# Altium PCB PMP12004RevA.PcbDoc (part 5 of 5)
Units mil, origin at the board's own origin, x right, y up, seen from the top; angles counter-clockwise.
Board outline 5500 x 4500 mil, 6 copper layers (Top Layer, GND, Signal Layer 1, Signal Layer 2, PWR Split, Bottom Layer), stack 0 mil thick; 355 components, 130 nets, 833 pads, 904 vias.
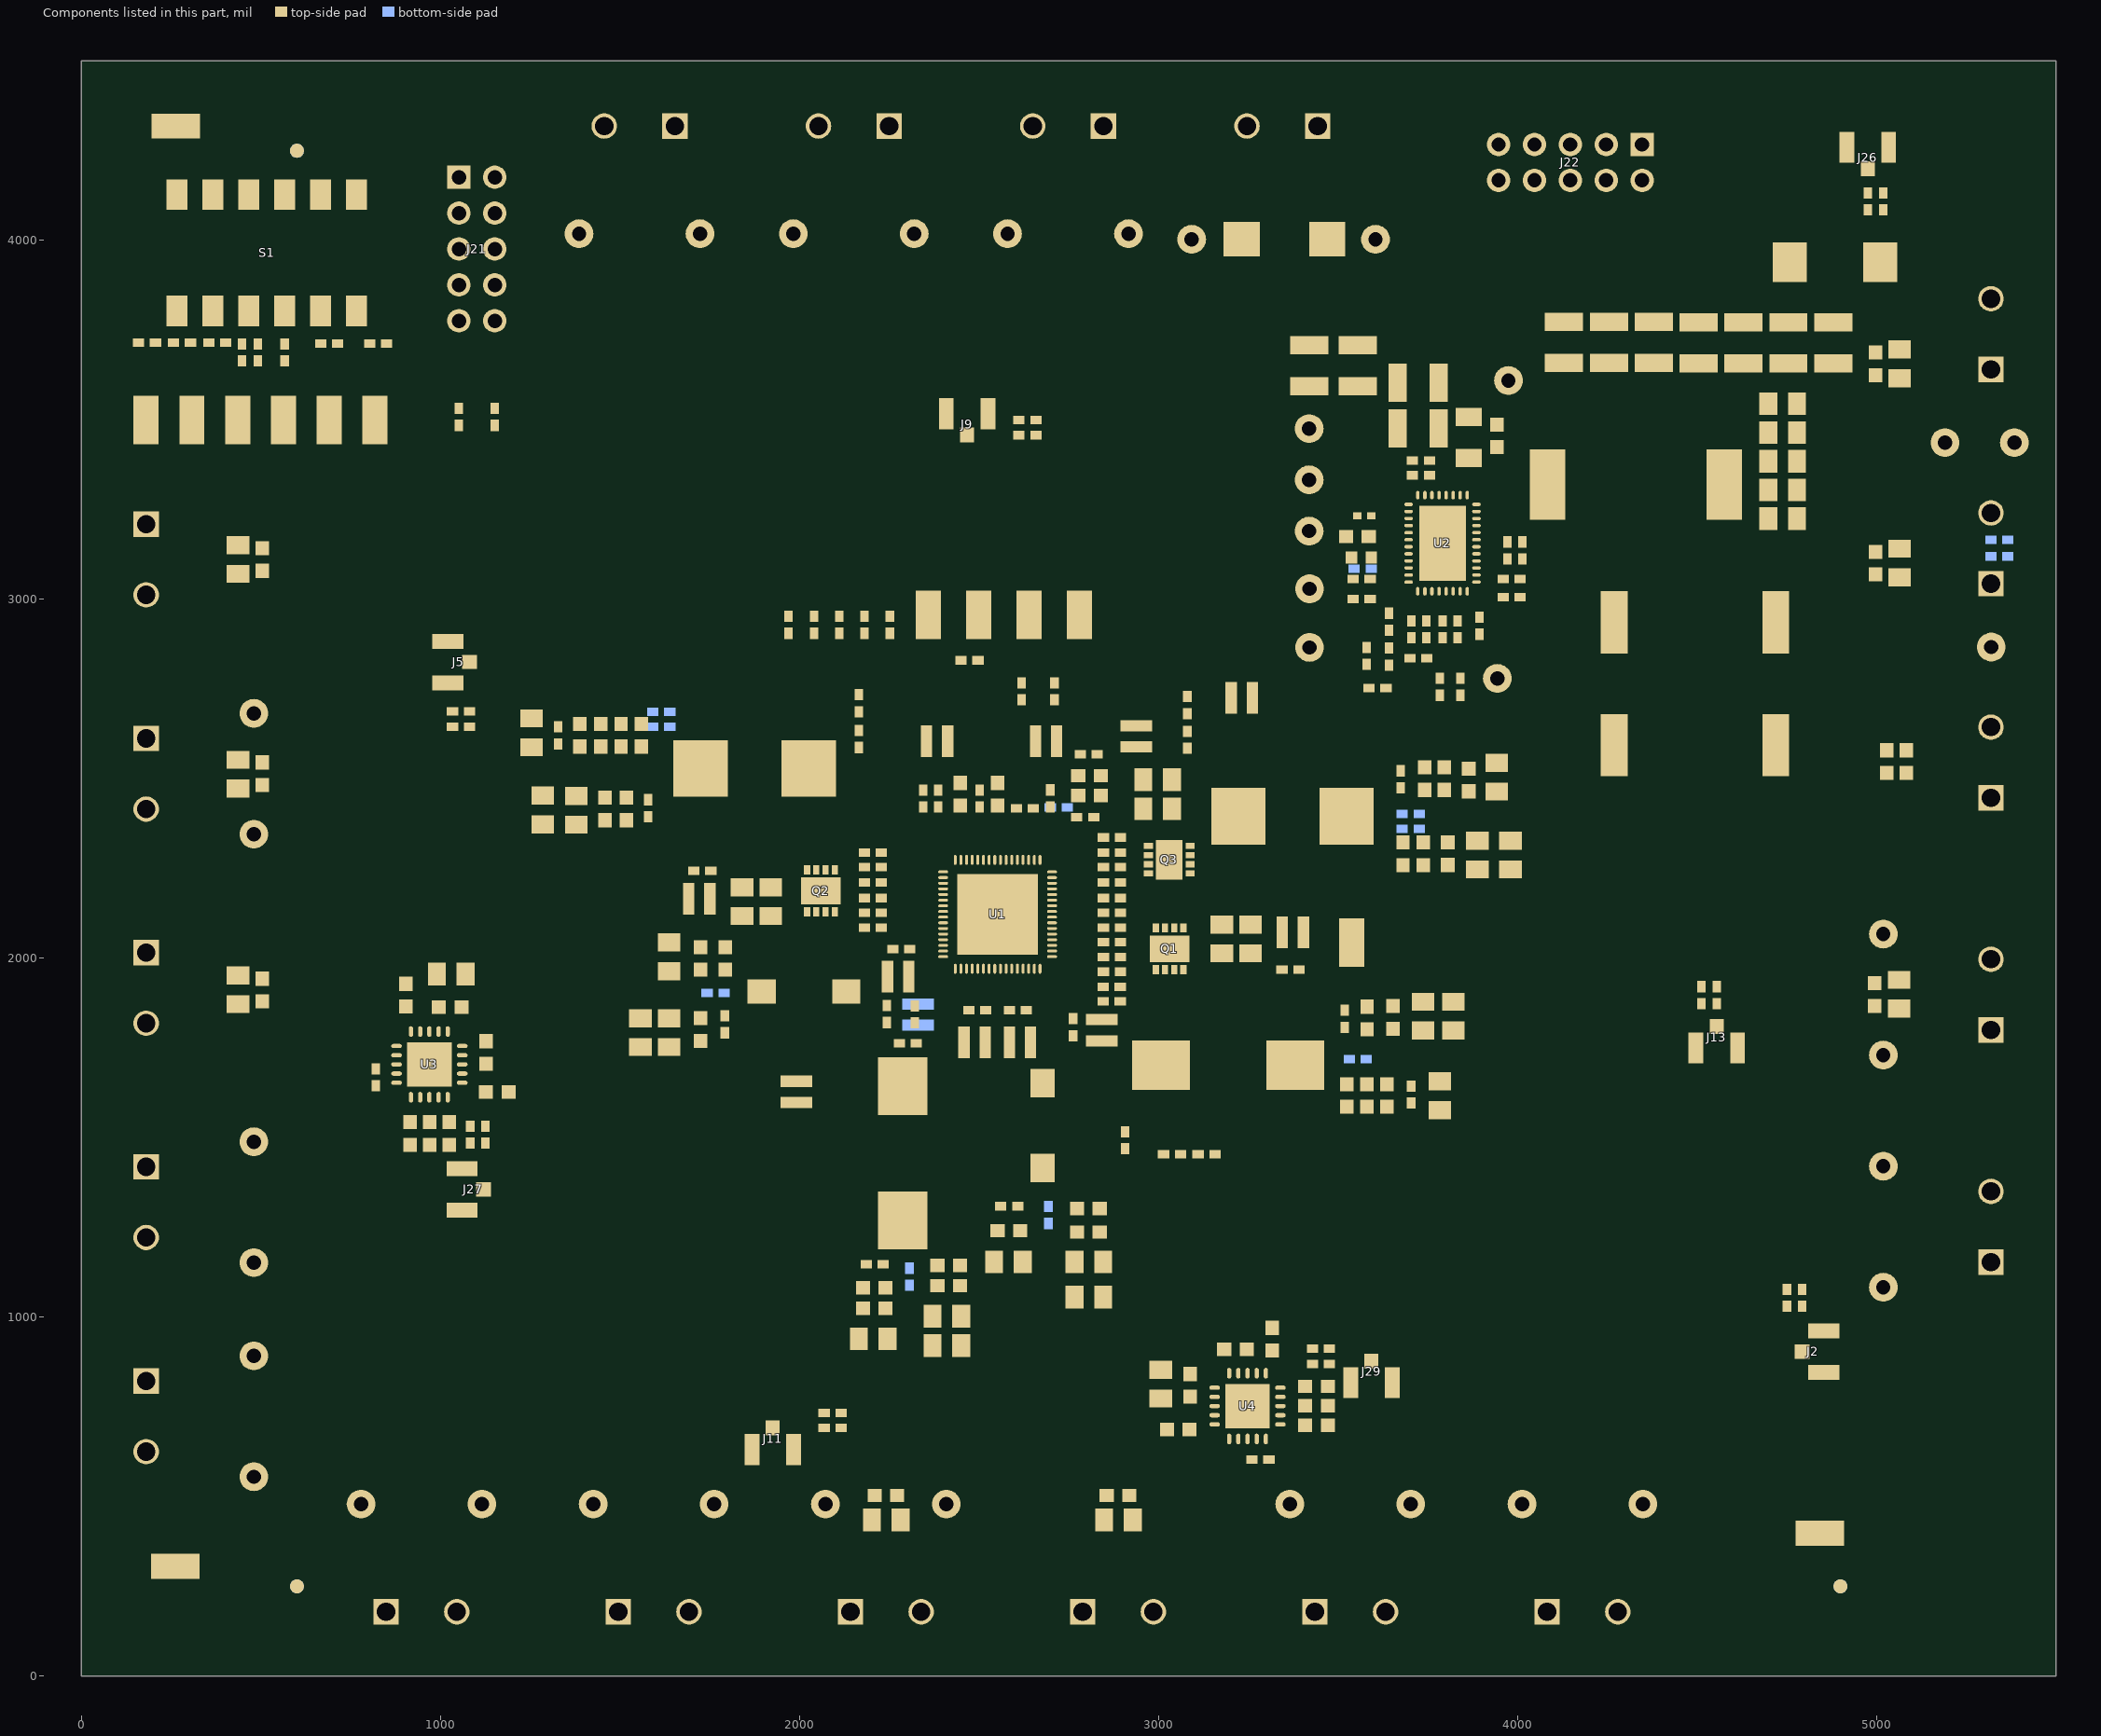
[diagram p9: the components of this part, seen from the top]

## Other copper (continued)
PWR Split:
  pour cut-out: 1335.59,4019 1337.31,4032.05 1342.35,4044.22 1350.36,4054.66 1360.81,4062.67 1372.97,4067.71 1386.02,4069.43 1399.08,4067.71 1411.24,4062.67 1421.69,4054.66 1429.7,4044.22 1434.74,4032.05 1436.46,4019 1434.74,4005.95 1429.7,3993.78 1421.69,3983.34 1411.24,3975.33 1399.08,3970.29 1386.02,3968.57 1372.97,3970.29 1360.81,3975.33 1350.36,3983.34 1342.35,3993.78 1337.31,4005.95
  pour cut-out: 1672.44,4019 1674.16,4032.05 1679.2,4044.22 1687.21,4054.66 1697.66,4062.67 1709.82,4067.71 1722.87,4069.43 1735.93,4067.71 1748.09,4062.67 1758.54,4054.66 1766.55,4044.22 1771.59,4032.05 1773.31,4019 1771.59,4005.95 1766.55,3993.78 1758.54,3983.34 1748.09,3975.33 1735.93,3970.29 1722.87,3968.57 1709.82,3970.29 1697.66,3975.33 1687.21,3983.34 1679.2,3993.78 1674.16,4005.95
  pour cut-out: 1932.44,4019 1934.16,4032.05 1939.2,4044.22 1947.21,4054.66 1957.66,4062.67 1969.82,4067.71 1982.87,4069.43 1995.93,4067.71 2008.09,4062.67 2018.54,4054.66 2026.55,4044.22 2031.59,4032.05 2033.31,4019 2031.59,4005.95 2026.55,3993.78 2018.54,3983.34 2008.09,3975.33 1995.93,3970.29 1982.87,3968.57 1969.82,3970.29 1957.66,3975.33 1947.21,3983.34 1939.2,3993.78 1934.16,4005.95
  pour cut-out: 2269.29,4019 2271.01,4032.05 2276.05,4044.22 2284.06,4054.66 2294.51,4062.67 2306.67,4067.71 2319.72,4069.43 2332.78,4067.71 2344.94,4062.67 2355.39,4054.66 2363.4,4044.22 2368.44,4032.05 2370.16,4019 2368.44,4005.95 2363.4,3993.78 2355.39,3983.34 2344.94,3975.33 2332.78,3970.29 2319.72,3968.57 2306.67,3970.29 2294.51,3975.33 2284.06,3983.34 2276.05,3993.78 2271.01,4005.95
  pour cut-out: 2529.29,4019 2531.01,4032.05 2536.05,4044.22 2544.06,4054.66 2554.51,4062.67 2566.67,4067.71 2579.72,4069.43 2592.78,4067.71 2604.94,4062.67 2615.39,4054.66 2623.4,4044.22 2628.44,4032.05 2630.16,4019 2628.44,4005.95 2623.4,3993.78 2615.39,3983.34 2604.94,3975.33 2592.78,3970.29 2579.72,3968.57 2566.67,3970.29 2554.51,3975.33 2544.06,3983.34 2536.05,3993.78 2531.01,4005.95
  pour cut-out: 2866.14,4019 2867.86,4032.05 2872.9,4044.22 2880.91,4054.66 2891.36,4062.67 2903.52,4067.71 2916.57,4069.43 2929.63,4067.71 2941.79,4062.67 2952.24,4054.66 2960.25,4044.22 2965.29,4032.05 2967.01,4019 2965.29,4005.95 2960.25,3993.78 2952.24,3983.34 2941.79,3975.33 2929.63,3970.29 2916.57,3968.57 2903.52,3970.29 2891.36,3975.33 2880.91,3983.34 2872.9,3993.78 2867.86,4005.95
  pour cut-out: 4968.9,2067.19 4970.62,2080.25 4975.66,2092.41 4983.67,2102.85 4994.12,2110.87 5006.28,2115.91 5019.33,2117.63 5032.38,2115.91 5044.55,2110.87 5054.99,2102.85 5063.01,2092.41 5068.05,2080.25 5069.76,2067.19 5068.05,2054.14 5063.01,2041.98 5054.99,2031.53 5044.55,2023.52 5032.38,2018.48 5019.33,2016.76 5006.28,2018.48 4994.12,2023.52 4983.67,2031.53 4975.66,2041.98 4970.62,2054.14
  pour cut-out: 4968.9,1730.34 4970.62,1743.4 4975.66,1755.56 4983.67,1766 4994.12,1774.02 5006.28,1779.06 5019.33,1780.78 5032.38,1779.06 5044.55,1774.02 5054.99,1766 5063.01,1755.56 5068.05,1743.4 5069.76,1730.34 5068.05,1717.29 5063.01,1705.13 5054.99,1694.68 5044.55,1686.67 5032.38,1681.63 5019.33,1679.91 5006.28,1681.63 4994.12,1686.67 4983.67,1694.68 4975.66,1705.13 4970.62,1717.29
  pour cut-out: 4968.9,1420.34 4970.62,1433.4 4975.66,1445.56 4983.67,1456 4994.12,1464.02 5006.28,1469.06 5019.33,1470.78 5032.38,1469.06 5044.55,1464.02 5054.99,1456 5063.01,1445.56 5068.05,1433.4 5069.76,1420.34 5068.05,1407.29 5063.01,1395.13 5054.99,1384.68 5044.55,1376.67 5032.38,1371.63 5019.33,1369.91 5006.28,1371.63 4994.12,1376.67 4983.67,1384.68 4975.66,1395.13 4970.62,1407.29
  pour cut-out: 4968.9,1083.49 4970.62,1096.55 4975.66,1108.71 4983.67,1119.15 4994.12,1127.17 5006.28,1132.21 5019.33,1133.93 5032.38,1132.21 5044.55,1127.17 5054.99,1119.15 5063.01,1108.71 5068.05,1096.55 5069.76,1083.49 5068.05,1070.44 5063.01,1058.28 5054.99,1047.83 5044.55,1039.82 5032.38,1034.78 5019.33,1033.06 5006.28,1034.78 4994.12,1039.82 4983.67,1047.83 4975.66,1058.28 4970.62,1070.44
  pour cut-out: 4299.24,479 4300.96,492.05 4306,504.22 4314.01,514.66 4324.46,522.67 4336.62,527.71 4349.68,529.43 4362.73,527.71 4374.89,522.67 4385.34,514.66 4393.35,504.22 4398.39,492.05 4400.11,479 4398.39,465.95 4393.35,453.78 4385.34,443.34 4374.89,435.33 4362.73,430.29 4349.68,428.57 4336.62,430.29 4324.46,435.33 4314.01,443.34 4306,453.78 4300.96,465.95
  pour cut-out: 3962.39,479 3964.11,492.05 3969.15,504.22 3977.16,514.66 3987.61,522.67 3999.77,527.71 4012.83,529.43 4025.88,527.71 4038.04,522.67 4048.49,514.66 4056.5,504.22 4061.54,492.05 4063.26,479 4061.54,465.95 4056.5,453.78 4048.49,443.34 4038.04,435.33 4025.88,430.29 4012.83,428.57 3999.77,430.29 3987.61,435.33 3977.16,443.34 3969.15,453.78 3964.11,465.95
  pour cut-out: 3652.39,479 3654.11,492.05 3659.15,504.22 3667.16,514.66 3677.61,522.67 3689.77,527.71 3702.83,529.43 3715.88,527.71 3728.04,522.67 3738.49,514.66 3746.5,504.22 3751.54,492.05 3753.26,479 3751.54,465.95 3746.5,453.78 3738.49,443.34 3728.04,435.33 3715.88,430.29 3702.83,428.57 3689.77,430.29 3677.61,435.33 3667.16,443.34 3659.15,453.78 3654.11,465.95
  pour cut-out: 3315.54,479 3317.26,492.05 3322.3,504.22 3330.31,514.66 3340.76,522.67 3352.92,527.71 3365.98,529.43 3379.03,527.71 3391.19,522.67 3401.64,514.66 3409.65,504.22 3414.69,492.05 3416.41,479 3414.69,465.95 3409.65,453.78 3401.64,443.34 3391.19,435.33 3379.03,430.29 3365.98,428.57 3352.92,430.29 3340.76,435.33 3330.31,443.34 3322.3,453.78 3317.26,465.95
  pour cut-out: 2358.69,479 2360.41,492.05 2365.45,504.22 2373.46,514.66 2383.91,522.67 2396.07,527.71 2409.13,529.43 2422.18,527.71 2434.34,522.67 2444.79,514.66 2452.8,504.22 2457.84,492.05 2459.56,479 2457.84,465.95 2452.8,453.78 2444.79,443.34 2434.34,435.33 2422.18,430.29 2409.13,428.57 2396.07,430.29 2383.91,435.33 2373.46,443.34 2365.45,453.78 2360.41,465.95
  pour cut-out: 2021.84,479 2023.56,492.05 2028.6,504.22 2036.61,514.66 2047.06,522.67 2059.22,527.71 2072.28,529.43 2085.33,527.71 2097.49,522.67 2107.94,514.66 2115.95,504.22 2120.99,492.05 2122.71,479 2120.99,465.95 2115.95,453.78 2107.94,443.34 2097.49,435.33 2085.33,430.29 2072.28,428.57 2059.22,430.29 2047.06,435.33 2036.61,443.34 2028.6,453.78 2023.56,465.95
  pour cut-out: 1711.84,479 1713.56,492.05 1718.6,504.22 1726.61,514.66 1737.06,522.67 1749.22,527.71 1762.28,529.43 1775.33,527.71 1787.49,522.67 1797.94,514.66 1805.95,504.22 1810.99,492.05 1812.71,479 1810.99,465.95 1805.95,453.78 1797.94,443.34 1787.49,435.33 1775.33,430.29 1762.28,428.57 1749.22,430.29 1737.06,435.33 1726.61,443.34 1718.6,453.78 1713.56,465.95
  pour cut-out: 1374.99,479 1376.71,492.05 1381.75,504.22 1389.76,514.66 1400.21,522.67 1412.37,527.71 1425.43,529.43 1438.48,527.71 1450.64,522.67 1461.09,514.66 1469.1,504.22 1474.14,492.05 1475.86,479 1474.14,465.95 1469.1,453.78 1461.09,443.34 1450.64,435.33 1438.48,430.29 1425.43,428.57 1412.37,430.29 1400.21,435.33 1389.76,443.34 1381.75,453.78 1376.71,465.95
  pour cut-out: 1064.99,479 1066.71,492.05 1071.75,504.22 1079.76,514.66 1090.21,522.67 1102.37,527.71 1115.43,529.43 1128.48,527.71 1140.64,522.67 1151.09,514.66 1159.1,504.22 1164.14,492.05 1165.86,479 1164.14,465.95 1159.1,453.78 1151.09,443.34 1140.64,435.33 1128.48,430.29 1115.43,428.57 1102.37,430.29 1090.21,435.33 1079.76,443.34 1071.75,453.78 1066.71,465.95
  pour cut-out: 728.14,479 729.86,492.05 734.9,504.22 742.91,514.66 753.36,522.67 765.52,527.71 778.58,529.43 791.63,527.71 803.79,522.67 814.24,514.66 822.25,504.22 827.29,492.05 829.01,479 827.29,465.95 822.25,453.78 814.24,443.34 803.79,435.33 791.63,430.29 778.58,428.57 765.52,430.29 753.36,435.33 742.91,443.34 734.9,453.78 729.86,465.95
  pour cut-out: 429.57,555.17 431.29,568.23 436.33,580.39 444.34,590.84 454.78,598.85 466.95,603.89 480,605.61 493.05,603.89 505.22,598.85 515.66,590.84 523.67,580.39 528.71,568.23 530.43,555.17 528.71,542.12 523.67,529.96 515.66,519.51 505.22,511.5 493.05,506.46 480,504.74 466.95,506.46 454.78,511.5 444.34,519.51 436.33,529.96 431.29,542.12
  pour cut-out: 429.57,892.02 431.29,905.08 436.33,917.24 444.34,927.69 454.78,935.7 466.95,940.74 480,942.46 493.05,940.74 505.22,935.7 515.66,927.69 523.67,917.24 528.71,905.08 530.43,892.02 528.71,878.97 523.67,866.81 515.66,856.36 505.22,848.35 493.05,843.31 480,841.59 466.95,843.31 454.78,848.35 444.34,856.36 436.33,866.81 431.29,878.97
  pour cut-out: 429.57,1488.87 431.29,1501.93 436.33,1514.09 444.34,1524.54 454.78,1532.55 466.95,1537.59 480,1539.31 493.05,1537.59 505.22,1532.55 515.66,1524.54 523.67,1514.09 528.71,1501.93 530.43,1488.87 528.71,1475.82 523.67,1463.66 515.66,1453.21 505.22,1445.2 493.05,1440.16 480,1438.44 466.95,1440.16 454.78,1445.2 444.34,1453.21 436.33,1463.66 431.29,1475.82
  pour cut-out: 429.57,2345.72 431.29,2358.78 436.33,2370.94 444.34,2381.39 454.78,2389.4 466.95,2394.44 480,2396.16 493.05,2394.44 505.22,2389.4 515.66,2381.39 523.67,2370.94 528.71,2358.78 530.43,2345.72 528.71,2332.67 523.67,2320.51 515.66,2310.06 505.22,2302.05 493.05,2297.01 480,2295.29 466.95,2297.01 454.78,2302.05 444.34,2310.06 436.33,2320.51 431.29,2332.67
  pour cut-out: 429.57,2682.57 431.29,2695.63 436.33,2707.79 444.34,2718.24 454.78,2726.25 466.95,2731.29 480,2733.01 493.05,2731.29 505.22,2726.25 515.66,2718.24 523.67,2707.79 528.71,2695.63 530.43,2682.57 528.71,2669.52 523.67,2657.36 515.66,2646.91 505.22,2638.9 493.05,2633.86 480,2632.14 466.95,2633.86 454.78,2638.9 444.34,2646.91 436.33,2657.36 431.29,2669.52
  pour cut-out: 429.57,1152.02 431.29,1165.08 436.33,1177.24 444.34,1187.69 454.78,1195.7 466.95,1200.74 480,1202.46 493.05,1200.74 505.22,1195.7 515.66,1187.69 523.67,1177.24 528.71,1165.08 530.43,1152.02 528.71,1138.97 523.67,1126.81 515.66,1116.36 505.22,1108.35 493.05,1103.31 480,1101.59 466.95,1103.31 454.78,1108.35 444.34,1116.36 436.33,1126.81 431.29,1138.97
  pour cut-out: 1444.93,2268.2 1558.11,2268.2 1569.61,2279.69 1569.61,2366.5 1559.01,2377.09 1545.94,2377.09 1445.6,2276.75 1444.92,2276.75
  pour cut-out: 2532.84,1730.68 2747.78,1730.68 2748.24,1731.15 2656.78,1822.6 2656.78,1864.67 2648.85,1872.61 2648.85,1998.45 2675.49,2025.09 2818.34,2025.09 2820.61,2027.36 2820.61,2037.57 2800.2,2057.97 2800.2,2104.74 2791.98,2112.96 2783.48,2112.96 2739.8,2069.28 2476.84,2069.28 2345.01,2201.11 2327.72,2201.11 2319.5,2192.89 2319.5,2062.49 2325.16,2056.83 2376.76,2056.83 2436.56,1997.03 2436.56,1949.98 2449.03,1937.51 2484.74,1937.51 2546.25,1876.01 2546.25,1744.78 2531.79,1730.32
  pour cut-out: 3155.1,2453.18 3155.1,2345.39 3141.1,2331.39 3061.33,2331.39 3056.27,2326.34 3056.27,2311.55 3051.22,2306.49 3022.42,2306.49 3018.92,2309.99 3018.92,2325.17 3139.93,2446.18
  pour cut-out: 2835.72,2627.54 2919.59,2543.68 2920.05,2543.68 2920.05,2538.59 2855.25,2473.78 2833.66,2473.78 2833.66,2624.34 2835.72,2626.4
  pour cut-out: 3267.37,1924.06 3041.13,1924.06 2954.53,2010.66 2954.53,2024.78 3177.37,2024.78 3267.4,1934.74 3267.4,1929.64
  pour cut-out: 3422.52,1896.68 3639.23,1896.68 3658.35,1915.8 3658.35,1936.09 3654.08,1940.36 3631.85,1940.36 3622.58,1931.09 3513.35,1931.09 3491.43,1909.17 3426.77,1909.17 3422.61,1905
  pour cut-out: 1089.62,1962.7 1100.02,1952.3 1132.01,1952.3 1144.31,1964.61 1138.87,1970.05 1093.41,1970.05 1089.63,1966.26
  pour cut-out: 5269.66,2867.18 5271.38,2880.23 5276.42,2892.39 5284.43,2902.84 5294.87,2910.85 5307.04,2915.89 5320.09,2917.61 5333.14,2915.89 5345.31,2910.85 5355.75,2902.84 5363.76,2892.39 5368.8,2880.23 5370.52,2867.18 5368.8,2854.12 5363.76,2841.96 5355.75,2831.52 5345.31,2823.5 5333.14,2818.46 5320.09,2816.74 5307.04,2818.46 5294.87,2823.5 5284.43,2831.52 5276.42,2841.96 5271.38,2854.12
  pour cut-out: 2542.72,3561.02 2568.8,3561.02 2584.46,3545.36 2584.46,3520.88 2577.7,3520.88 2542.84,3555.73
  pour cut-out: 521.85,836.9 542.93,857.99 543.22,857.99 546.89,854.32 546.89,843.6 535.88,832.59 525.44,832.59
  text "5" at 5162.44,637.86 h100
  text ".Layer_Name" at 577,-858.49 h60
Bottom Layer:
  pour cut-out: 5293.59,3144.07 5324.82,3144.07 5337.45,3131.44 5337.45,3079.69 5291.24,3079.69 5291.24,3141.71
  pour cut-out: 1335.59,4019 1337.31,4032.05 1342.35,4044.22 1350.36,4054.66 1360.81,4062.67 1372.97,4067.71 1386.02,4069.43 1399.08,4067.71 1411.24,4062.67 1421.69,4054.66 1429.7,4044.22 1434.74,4032.05 1436.46,4019 1434.74,4005.95 1429.7,3993.78 1421.69,3983.34 1411.24,3975.33 1399.08,3970.29 1386.02,3968.57 1372.97,3970.29 1360.81,3975.33 1350.36,3983.34 1342.35,3993.78 1337.31,4005.95
  pour cut-out: 1672.44,4019 1674.16,4032.05 1679.2,4044.22 1687.21,4054.66 1697.66,4062.67 1709.82,4067.71 1722.87,4069.43 1735.93,4067.71 1748.09,4062.67 1758.54,4054.66 1766.55,4044.22 1771.59,4032.05 1773.31,4019 1771.59,4005.95 1766.55,3993.78 1758.54,3983.34 1748.09,3975.33 1735.93,3970.29 1722.87,3968.57 1709.82,3970.29 1697.66,3975.33 1687.21,3983.34 1679.2,3993.78 1674.16,4005.95
  pour cut-out: 1932.44,4019 1934.16,4032.05 1939.2,4044.22 1947.21,4054.66 1957.66,4062.67 1969.82,4067.71 1982.87,4069.43 1995.93,4067.71 2008.09,4062.67 2018.54,4054.66 2026.55,4044.22 2031.59,4032.05 2033.31,4019 2031.59,4005.95 2026.55,3993.78 2018.54,3983.34 2008.09,3975.33 1995.93,3970.29 1982.87,3968.57 1969.82,3970.29 1957.66,3975.33 1947.21,3983.34 1939.2,3993.78 1934.16,4005.95
  pour cut-out: 2269.29,4019 2271.01,4032.05 2276.05,4044.22 2284.06,4054.66 2294.51,4062.67 2306.67,4067.71 2319.72,4069.43 2332.78,4067.71 2344.94,4062.67 2355.39,4054.66 2363.4,4044.22 2368.44,4032.05 2370.16,4019 2368.44,4005.95 2363.4,3993.78 2355.39,3983.34 2344.94,3975.33 2332.78,3970.29 2319.72,3968.57 2306.67,3970.29 2294.51,3975.33 2284.06,3983.34 2276.05,3993.78 2271.01,4005.95
  pour cut-out: 2529.29,4019 2531.01,4032.05 2536.05,4044.22 2544.06,4054.66 2554.51,4062.67 2566.67,4067.71 2579.72,4069.43 2592.78,4067.71 2604.94,4062.67 2615.39,4054.66 2623.4,4044.22 2628.44,4032.05 2630.16,4019 2628.44,4005.95 2623.4,3993.78 2615.39,3983.34 2604.94,3975.33 2592.78,3970.29 2579.72,3968.57 2566.67,3970.29 2554.51,3975.33 2544.06,3983.34 2536.05,3993.78 2531.01,4005.95
  pour cut-out: 2866.14,4019 2867.86,4032.05 2872.9,4044.22 2880.91,4054.66 2891.36,4062.67 2903.52,4067.71 2916.57,4069.43 2929.63,4067.71 2941.79,4062.67 2952.24,4054.66 2960.25,4044.22 2965.29,4032.05 2967.01,4019 2965.29,4005.95 2960.25,3993.78 2952.24,3983.34 2941.79,3975.33 2929.63,3970.29 2916.57,3968.57 2903.52,3970.29 2891.36,3975.33 2880.91,3983.34 2872.9,3993.78 2867.86,4005.95
  pour cut-out: 4968.9,2067.19 4970.62,2080.25 4975.66,2092.41 4983.67,2102.85 4994.12,2110.87 5006.28,2115.91 5019.33,2117.63 5032.38,2115.91 5044.55,2110.87 5054.99,2102.85 5063.01,2092.41 5068.05,2080.25 5069.76,2067.19 5068.05,2054.14 5063.01,2041.98 5054.99,2031.53 5044.55,2023.52 5032.38,2018.48 5019.33,2016.76 5006.28,2018.48 4994.12,2023.52 4983.67,2031.53 4975.66,2041.98 4970.62,2054.14
  pour cut-out: 4968.9,1730.34 4970.62,1743.4 4975.66,1755.56 4983.67,1766 4994.12,1774.02 5006.28,1779.06 5019.33,1780.78 5032.38,1779.06 5044.55,1774.02 5054.99,1766 5063.01,1755.56 5068.05,1743.4 5069.76,1730.34 5068.05,1717.29 5063.01,1705.13 5054.99,1694.68 5044.55,1686.67 5032.38,1681.63 5019.33,1679.91 5006.28,1681.63 4994.12,1686.67 4983.67,1694.68 4975.66,1705.13 4970.62,1717.29
  pour cut-out: 4968.9,1420.34 4970.62,1433.4 4975.66,1445.56 4983.67,1456 4994.12,1464.02 5006.28,1469.06 5019.33,1470.78 5032.38,1469.06 5044.55,1464.02 5054.99,1456 5063.01,1445.56 5068.05,1433.4 5069.76,1420.34 5068.05,1407.29 5063.01,1395.13 5054.99,1384.68 5044.55,1376.67 5032.38,1371.63 5019.33,1369.91 5006.28,1371.63 4994.12,1376.67 4983.67,1384.68 4975.66,1395.13 4970.62,1407.29
  pour cut-out: 4968.9,1083.49 4970.62,1096.55 4975.66,1108.71 4983.67,1119.15 4994.12,1127.17 5006.28,1132.21 5019.33,1133.93 5032.38,1132.21 5044.55,1127.17 5054.99,1119.15 5063.01,1108.71 5068.05,1096.55 5069.76,1083.49 5068.05,1070.44 5063.01,1058.28 5054.99,1047.83 5044.55,1039.82 5032.38,1034.78 5019.33,1033.06 5006.28,1034.78 4994.12,1039.82 4983.67,1047.83 4975.66,1058.28 4970.62,1070.44
  pour cut-out: 4299.24,479 4300.96,492.05 4306,504.22 4314.01,514.66 4324.46,522.67 4336.62,527.71 4349.68,529.43 4362.73,527.71 4374.89,522.67 4385.34,514.66 4393.35,504.22 4398.39,492.05 4400.11,479 4398.39,465.95 4393.35,453.78 4385.34,443.34 4374.89,435.33 4362.73,430.29 4349.68,428.57 4336.62,430.29 4324.46,435.33 4314.01,443.34 4306,453.78 4300.96,465.95
  pour cut-out: 3962.39,479 3964.11,492.05 3969.15,504.22 3977.16,514.66 3987.61,522.67 3999.77,527.71 4012.83,529.43 4025.88,527.71 4038.04,522.67 4048.49,514.66 4056.5,504.22 4061.54,492.05 4063.26,479 4061.54,465.95 4056.5,453.78 4048.49,443.34 4038.04,435.33 4025.88,430.29 4012.83,428.57 3999.77,430.29 3987.61,435.33 3977.16,443.34 3969.15,453.78 3964.11,465.95
  pour cut-out: 3652.39,479 3654.11,492.05 3659.15,504.22 3667.16,514.66 3677.61,522.67 3689.77,527.71 3702.83,529.43 3715.88,527.71 3728.04,522.67 3738.49,514.66 3746.5,504.22 3751.54,492.05 3753.26,479 3751.54,465.95 3746.5,453.78 3738.49,443.34 3728.04,435.33 3715.88,430.29 3702.83,428.57 3689.77,430.29 3677.61,435.33 3667.16,443.34 3659.15,453.78 3654.11,465.95
  pour cut-out: 3315.54,479 3317.26,492.05 3322.3,504.22 3330.31,514.66 3340.76,522.67 3352.92,527.71 3365.98,529.43 3379.03,527.71 3391.19,522.67 3401.64,514.66 3409.65,504.22 3414.69,492.05 3416.41,479 3414.69,465.95 3409.65,453.78 3401.64,443.34 3391.19,435.33 3379.03,430.29 3365.98,428.57 3352.92,430.29 3340.76,435.33 3330.31,443.34 3322.3,453.78 3317.26,465.95
  pour cut-out: 2358.69,479 2360.41,492.05 2365.45,504.22 2373.46,514.66 2383.91,522.67 2396.07,527.71 2409.13,529.43 2422.18,527.71 2434.34,522.67 2444.79,514.66 2452.8,504.22 2457.84,492.05 2459.56,479 2457.84,465.95 2452.8,453.78 2444.79,443.34 2434.34,435.33 2422.18,430.29 2409.13,428.57 2396.07,430.29 2383.91,435.33 2373.46,443.34 2365.45,453.78 2360.41,465.95
  pour cut-out: 2021.84,479 2023.56,492.05 2028.6,504.22 2036.61,514.66 2047.06,522.67 2059.22,527.71 2072.28,529.43 2085.33,527.71 2097.49,522.67 2107.94,514.66 2115.95,504.22 2120.99,492.05 2122.71,479 2120.99,465.95 2115.95,453.78 2107.94,443.34 2097.49,435.33 2085.33,430.29 2072.28,428.57 2059.22,430.29 2047.06,435.33 2036.61,443.34 2028.6,453.78 2023.56,465.95
  pour cut-out: 1711.84,479 1713.56,492.05 1718.6,504.22 1726.61,514.66 1737.06,522.67 1749.22,527.71 1762.28,529.43 1775.33,527.71 1787.49,522.67 1797.94,514.66 1805.95,504.22 1810.99,492.05 1812.71,479 1810.99,465.95 1805.95,453.78 1797.94,443.34 1787.49,435.33 1775.33,430.29 1762.28,428.57 1749.22,430.29 1737.06,435.33 1726.61,443.34 1718.6,453.78 1713.56,465.95
  pour cut-out: 1374.99,479 1376.71,492.05 1381.75,504.22 1389.76,514.66 1400.21,522.67 1412.37,527.71 1425.43,529.43 1438.48,527.71 1450.64,522.67 1461.09,514.66 1469.1,504.22 1474.14,492.05 1475.86,479 1474.14,465.95 1469.1,453.78 1461.09,443.34 1450.64,435.33 1438.48,430.29 1425.43,428.57 1412.37,430.29 1400.21,435.33 1389.76,443.34 1381.75,453.78 1376.71,465.95
  pour cut-out: 1064.99,479 1066.71,492.05 1071.75,504.22 1079.76,514.66 1090.21,522.67 1102.37,527.71 1115.43,529.43 1128.48,527.71 1140.64,522.67 1151.09,514.66 1159.1,504.22 1164.14,492.05 1165.86,479 1164.14,465.95 1159.1,453.78 1151.09,443.34 1140.64,435.33 1128.48,430.29 1115.43,428.57 1102.37,430.29 1090.21,435.33 1079.76,443.34 1071.75,453.78 1066.71,465.95
  pour cut-out: 728.14,479 729.86,492.05 734.9,504.22 742.91,514.66 753.36,522.67 765.52,527.71 778.58,529.43 791.63,527.71 803.79,522.67 814.24,514.66 822.25,504.22 827.29,492.05 829.01,479 827.29,465.95 822.25,453.78 814.24,443.34 803.79,435.33 791.63,430.29 778.58,428.57 765.52,430.29 753.36,435.33 742.91,443.34 734.9,453.78 729.86,465.95
  pour cut-out: 429.57,555.17 431.29,568.23 436.33,580.39 444.34,590.84 454.78,598.85 466.95,603.89 480,605.61 493.05,603.89 505.22,598.85 515.66,590.84 523.67,580.39 528.71,568.23 530.43,555.17 528.71,542.12 523.67,529.96 515.66,519.51 505.22,511.5 493.05,506.46 480,504.74 466.95,506.46 454.78,511.5 444.34,519.51 436.33,529.96 431.29,542.12
  pour cut-out: 429.57,892.02 431.29,905.08 436.33,917.24 444.34,927.69 454.78,935.7 466.95,940.74 480,942.46 493.05,940.74 505.22,935.7 515.66,927.69 523.67,917.24 528.71,905.08 530.43,892.02 528.71,878.97 523.67,866.81 515.66,856.36 505.22,848.35 493.05,843.31 480,841.59 466.95,843.31 454.78,848.35 444.34,856.36 436.33,866.81 431.29,878.97
  pour cut-out: 429.57,1488.87 431.29,1501.93 436.33,1514.09 444.34,1524.54 454.78,1532.55 466.95,1537.59 480,1539.31 493.05,1537.59 505.22,1532.55 515.66,1524.54 523.67,1514.09 528.71,1501.93 530.43,1488.87 528.71,1475.82 523.67,1463.66 515.66,1453.21 505.22,1445.2 493.05,1440.16 480,1438.44 466.95,1440.16 454.78,1445.2 444.34,1453.21 436.33,1463.66 431.29,1475.82
  pour cut-out: 429.57,2345.72 431.29,2358.78 436.33,2370.94 444.34,2381.39 454.78,2389.4 466.95,2394.44 480,2396.16 493.05,2394.44 505.22,2389.4 515.66,2381.39 523.67,2370.94 528.71,2358.78 530.43,2345.72 528.71,2332.67 523.67,2320.51 515.66,2310.06 505.22,2302.05 493.05,2297.01 480,2295.29 466.95,2297.01 454.78,2302.05 444.34,2310.06 436.33,2320.51 431.29,2332.67
  pour cut-out: 429.57,2682.57 431.29,2695.63 436.33,2707.79 444.34,2718.24 454.78,2726.25 466.95,2731.29 480,2733.01 493.05,2731.29 505.22,2726.25 515.66,2718.24 523.67,2707.79 528.71,2695.63 530.43,2682.57 528.71,2669.52 523.67,2657.36 515.66,2646.91 505.22,2638.9 493.05,2633.86 480,2632.14 466.95,2633.86 454.78,2638.9 444.34,2646.91 436.33,2657.36 431.29,2669.52
  pour cut-out: 429.57,1152.02 431.29,1165.08 436.33,1177.24 444.34,1187.69 454.78,1195.7 466.95,1200.74 480,1202.46 493.05,1200.74 505.22,1195.7 515.66,1187.69 523.67,1177.24 528.71,1165.08 530.43,1152.02 528.71,1138.97 523.67,1126.81 515.66,1116.36 505.22,1108.35 493.05,1103.31 480,1101.59 466.95,1103.31 454.78,1108.35 444.34,1116.36 436.33,1126.81 431.29,1138.97
  pour cut-out: 1354.44,509.36 1354.44,439.89 1390.08,404.26 1546.78,404.26 1605.71,463.19 1605.71,1244.09 2074.64,1713.02 2239.37,1713.02 2270.07,1743.72 2270.07,1785.34 2260.19,1795.21 2237.97,1795.21 2227.6,1784.84 2227.6,1768.71 2215.51,1756.62 2051.77,1756.62 1557.94,1262.79 1557.94,519.21 1542.98,504.24 1493.95,504.24 1455.83,542.36 1387.45,542.36
  pour cut-out: 2138.36,2215.6 2300.22,2215.6 2327.24,2188.58 2297.69,2159.03 2281.56,2175.16 2138.36,2175.16
  pour cut-out: 2791.5,2138.15 2834.22,2138.15 2856.2,2160.13 2973.03,2160.13 3029.62,2216.72 3061.33,2185.01 2995.7,2119.37 2879.8,2119.37 2853.81,2093.38 2782.38,2093.38 2764.55,2111.2
  pour cut-out: 2785.08,2066.9 2833.02,2066.9 2854.29,2045.62 2952.65,2045.62 2952.65,1995.71 2815.66,1995.71 2785.08,2026.29
  pour cut-out: 5269.66,2867.18 5271.38,2880.23 5276.42,2892.39 5284.43,2902.84 5294.87,2910.85 5307.04,2915.89 5320.09,2917.61 5333.14,2915.89 5345.31,2910.85 5355.75,2902.84 5363.76,2892.39 5368.8,2880.23 5370.52,2867.18 5368.8,2854.12 5363.76,2841.96 5355.75,2831.52 5345.31,2823.5 5333.14,2818.46 5320.09,2816.74 5307.04,2818.46 5294.87,2823.5 5284.43,2831.52 5276.42,2841.96 5271.38,2854.12
  pour cut-out: 2310.49,2160.97 cw(c2310.49,2175.97) 2295.49,2175.97 cw(c2310.49,2175.97) 2310.49,2190.97 cw(c2310.49,2175.97) 2325.49,2175.97 cw(c2310.49,2175.97)
  pour cut-out: 2780.69,2112.34 cw(c2780.69,2127.34) 2765.69,2127.34 cw(c2780.69,2127.34) 2780.69,2142.34 cw(c2780.69,2127.34) 2795.69,2127.34 cw(c2780.69,2127.34)
  pour cut-out: 2785.08,2036.6 cw(c2785.08,2051.6) 2770.08,2051.6 cw(c2785.08,2051.6) 2785.08,2066.6 cw(c2785.08,2051.6) 2800.08,2051.6 cw(c2785.08,2051.6)
  pour cut-out: 3037.13,2179.63 cw(c3037.13,2194.63) 3022.13,2194.63 cw(c3037.13,2194.63) 3037.13,2209.63 cw(c3037.13,2194.63) 3052.13,2194.63 cw(c3037.13,2194.63)
  pour cut-out: 2952.65,2003.85 cw(c2952.65,2018.85) 2937.65,2018.85 cw(c2952.65,2018.85) 2952.65,2033.85 cw(c2952.65,2018.85) 2967.65,2018.85 cw(c2952.65,2018.85)
  pour cut-out: 2138.36,2180.07 cw(c2138.36,2195.07) 2123.36,2195.07 cw(c2138.36,2195.07) 2138.36,2210.07 cw(c2138.36,2195.07) 2153.36,2195.07 cw(c2138.36,2195.07)
  text "6" at 5382.44,636.86 h100
  text ".Layer_Name" at 577,-858.49 h60

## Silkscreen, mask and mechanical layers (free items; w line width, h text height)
Top Overlay:
  circle w6: c4074.91,1962.52 r32
  circle w6: c2774.33,2199.63 r32
  circle w6: c3643.02,3224.19 r25.32
  circle w6: c1961.21,3576 r25.32
  region: 1649.65,978.8 1349.65,978.8 1349.65,878.8 1649.65,878.8
  lines w6: 884.73,1432.65 893.19,1441.72 ; 3504.5,662.94 3520.44,647.01
  lines w6.1: 509.05,1697.24 642.16,1830.35 642.16,3186.72 520.72,3308.16 ; 1547.91,2101.3 1559.18,2090.03 1783.45,2090.03 ; 1678.82,1908.43 1684.07,1908.43 1700.78,1925.14 ; 1946.56,487.8 2024.33,565.57 2084.78,626.02 2976.17,626.02 ; 2119.08,2283.01 2138.71,2302.64 2138.71,2326.67 ; 2196.89,1735.87 2220.63,1759.61 2220.63,1782.89 ; 2592.42,1097.41 2592.42,996.88 2597.1,992.2 ; 2755.42,2600.64 2755.42,2724.12 2764.87,2733.56 ; 2804.83,1956.1 2772.67,1956.1 2728.49,2000.28 2728.49,2300.12 2789.87,2361.51 2805.58,2361.51 ; 2976.65,625.85 3114.62,487.87 ; 3494.98,2822.28 3510.69,2837.99 3543.81,2837.99 ; 3587.9,3253.84 3593.76,3259.7 3632.63,3259.7 3660.39,3259.7 3677.42,3242.67 3677.42,3203.83 3641.78,3168.2 3641.78,3028.37 3681.89,2988.26 3900.77,2988.26 3919.58,3007.07 3919.58,3072.46 3927.99,3080.87 ; 3686.08,3684.06 3686.08,3705.18 3702.32,3721.43 ; 4704.91,3832.23 4728.31,3832.23 4740.83,3819.72 ; 4798.75,3083.23 4813.8,3098.28 4813.8,3170.15 ; 1696.47,3486.78 1696.47,3719.37 1724.94,3747.84 1953.39,3747.84 2179.57,3521.67 2179.57,3424.8 2078.52,3323.75 1859.5,3323.75 1696.47,3486.78 ; 4021.19,1732.87 4021.19,2077.5 4100.2,2156.51 4183.89,2156.51 4238.31,2102.09 4238.31,1694.59 4203.54,1659.81 4094.25,1659.81 4021.19,1732.87
  lines w10: 5074.11,4023.23 5074.11,4085.31 5477.66,4085.31 ; 5075.67,2307.49 5075.67,2231.11 5481,2231.11
  text "GND" at 222.62,4376.69 h30
  text "VTT" at 2526.45,4316.49 h50 r90
  text "VSYS" at 3120.46,4266.51 h50 r90
  text "LDOA2" at 1832.92,4216.53 h50 r90
  text "LDOA3" at 1930.46,4216.53 h50 r90
  text "TPS544C25" at 5112.96,4205.05 h40
  text "1" at 261.39,4183.48 h30
  text "2" at 353.76,4183.48 h30
  text "3" at 452.78,4183.48 h30
  text "4" at 538.97,4183.48 h30
  text "5" at 652.29,4183.48 h30
  text "6" at 754.69,4183.48 h30
  text "_VOUT" at 5272.29,4134.98 h40
  text "VCCINT" at 5198.43,3968.77 h50
  text "GND" at 3567.22,3896.33 h30
  text "GND" at 2283.35,3862.82 h30
  text "GND" at 2884.56,3860.7 h30
  text "GND" at 1689.31,3857.7 h30
  text "B" at 1954.11,3563.22 h25
  text "VSYS" at 3228.89,3407.81 h30
  text "VOUTS+" at 4968.84,3357.31 h30
  text "CTL1" at 122.08,3330.57 h30
  text "CTL2" at 257.68,3330.57 h30
  text "CTL3" at 396.03,3330.57 h30
  text "CTL4" at 532.85,3330.57 h30
  text "CTL5" at 664.2,3330.57 h30
  text "CTL6" at 799.5,3330.57 h30
  text "SMBALERT" at 3127.9,3269.03 h30
  text "B" at 3635.29,3211.26 h25
  text "VREF" at 2815.11,3056.64 h30 r90
  text "LDO3P3" at 2677.15,3056.26 h30 r90
  text "V5ANA" at 2391.87,3054.99 h30 r90
  text "VSYS_IN" at 2536.8,3055.07 h30 r90
  text "VCCINT_IO" at 4943.95,2977.51 h50 r90
  text "VCCPSINTLP" at 18.55,2838.42 h50
  text "GND" at 5152.79,2808.03 h30
  text "GND" at 539.83,2727.36 h30
  text "BUCK2" at 736.81,2369.03 h50 r90
  text "VCCBRAM" at 5125.37,2266.94 h50
  text "VCCPSINTFP" at 18.55,2215.29 h50
  text "A" at 2764.2,2185.86 h30
  text "VCCODDR" at 5140.12,2124.02 h50
  text "A" at 4064.79,1948.75 h30
  text "BUCK6" at 4895,1867.2 h50 r90
  text "VCCPSDDR" at 18.55,1641.28 h50
  text "GND" at 4889.04,1591.65 h30
  text "3.3V@5A" at 5148.45,1477.14 h50
  text "GND" at 437.88,1385.51 h30
  text "BUCK3" at 634.92,1191.66 h50 r90
  text "BUCK1" at 4943.85,1142.72 h50 r90
  text "VMGTAVTT" at 18.55,1046.49 h50
  text "GND" at 4964.35,927.46 h30
  text ".PRJ_Number" at 783.67,898.81 h60
  text "-" at 1279.65,898.81 h60
  text "GND" at 441.11,789.71 h30
  text "XILINX RRH & WIRELESS BH" at 783.04,779.14 h60
  text ".PCB_Rev" at 787.55,678.06 h60
  text "BUCK5" at 2410.06,659.67 h50
  text "BUCK4" at 3416.88,535.49 h50
  text "GND" at 4087.05,446.4 h30
  text "LDOA1" at 25.84,427.9 h50
  text "GND" at 3418.65,403.6 h30
  text "GND" at 1385.41,378.46 h30
  text "GND" at 737.79,377.31 h30
  text "GND" at 2027.32,347.38 h30 r90
  text "GND" at 4803.41,308.77 h30
  text "SWB1" at 1223.94,58.72 h50 r90
  text "SWA1" at 4458.56,54.03 h50 r90
  text "SWB2" at 1870.4,49.35 h50 r90
  text "VCCPSPLL" at 2518.16,27.68 h50 r90
  text "VCCPSAUX" at 3164.58,27.68 h50 r90
  text "VMGTAVCC" at 3813.46,27.68 h50 r90
  text ".Layer_Name" at 577,-858.49 h60
Bottom Overlay:
  text ".Layer_Name" at 577,-858.49 h60
Top Paste:
  text ".Layer_Name" at 577,-858.49 h60
Bottom Paste:
  text ".Layer_Name" at 577,-858.49 h60
Top Solder:
  text ".Layer_Name" at 577,-858.49 h60
  text ".Layer_Name" at 577,-858.49 h60
Bottom Solder:
  text ".Layer_Name" at 577,-858.49 h60
Drill Guide:
  text ".Layer_Name" at 577,-858.49 h60
M1 Board Outline:
  the board outline again, w10
M2 Board Dimensions:
  rectangle: 383.26,-404.49 758.26,-279.49
  rectangle: 258.26,-279.49 383.26,-154.49
  lines w7: 258.26,-279.49 1258.26,-279.49 ; 383.26,-404.49 383.26,-154.49 ; 508.26,-404.49 508.26,-154.49 ; 758.26,-404.49 758.26,-154.49 ; 1008.26,-404.49 1008.26,-154.49 ; 258.26,-404.49 258.26,-154.49 1258.26,-154.49 1258.26,-404.49 258.26,-404.49
  lines w10: -92.71,-90.7 -17.08,-15.07 ; -49.84,-15.07 -17.08,-15.07 ; -17.08,-47.82 -17.08,-15.07
  text "(0,0)" at -251.39,-166.95 h50
M3 3D STEP Top:
  text ".Layer_Name" at 577,-858.49 h60
M4 3D STEP Bottom:
  text ".Layer_Name" at 577,-858.49 h60
M5 Assembly Top:
  lines w6.1: 1630.74,2285.06 2118.93,2285.06 2118.93,2773.27 1630.74,2773.27 1630.74,2285.06 ; 3129.33,2151.44 3129.33,2639.65 3617.52,2639.65 3617.52,2151.44 3129.33,2151.44
  lines w10: -292,-930.17 6308,-930.17 ; -292,-726.83 6310,-726.83 ; -292,-523.5 -292,-1133.5 3713,-1133.5 6310,-1133.5 6310,-523.5 -291.5,-523.5 -291.5,-1133.5 1284,-1133.5 ; 2173,-1133.5 2173,-523.5 ; 3440,-726.83 3440,-523.5 ; 4280,-726.83 4280,-523.5 ; 4902,-1140 4902,-937.17
  text "PCB VIEWED FROM TOP SIDE" at -228.5,-655.67 h60
  text "BOARD #:" at 2248,-655.67 h60
  text ".PRJ_Number" at 2793.5,-655.67 h60
  text "REV:" at 3638,-655.67 h60
  text ".PCB_Rev" at 3929.5,-655.67 h60
  text "SVN REV:" at 4476,-655.67 h60
  text ".VersionControl_RevNumber" at 4982,-655.67 h60
  text "LAYER NAME =" at -228.5,-858.49 h60
  text ".Layer_Name" at 577,-858.49 h60
  text "TID #:" at 2248,-859 h60
  text ".TID" at 2793.5,-859 h60
  text "GENERATED    :" at 2250,-1064.34 h60
  text ".Print_Date" at 3119.5,-1064.34 h60
  text ".Print_Time" at 3848.5,-1064.34 h60
  text "TEXAS INSTRUMENTS" at 5113,-1064.34 h60
M6 Assembly Bottom:
  lines w10: -292.5,-727.33 6309.5,-727.33 ; -290.5,-930.67 6309.5,-930.67 ; 1115.5,-1140.5 1115.5,-937.67 ; 1737.5,-727.33 1737.5,-524 ; 2577.5,-727.33 2577.5,-524 ; 3844.5,-1134 3844.5,-524 ; 4733.5,-1134 6309,-1134 6309,-524 -292.5,-524 -292.5,-1134 2304.5,-1134 6309.5,-1134 6309.5,-524
  text ".VersionControl_RevNumber" at 1035.5,-656.17 h60
  text "SVN REV:" at 1541.5,-656.17 h60
  text ".PCB_Rev" at 2088,-656.17 h60
  text "REV:" at 2379.5,-656.17 h60
  text ".PRJ_Number" at 3224,-656.17 h60
  text "BOARD #:" at 3769.5,-656.17 h60
  text "PCB VIEWED FROM BOTTOM SIDE" at 6246,-656.17 h60
  text ".TID" at 3224,-859.5 h60
  text "TID #:" at 3769.5,-859.5 h60
  text ".Layer_Name" at 5472.69,-864.21 h60
  text "LAYER NAME =" at 6245.57,-868.43 h60
  text "TEXAS INSTRUMENTS" at 904.5,-1064.84 h60
  text ".Print_Time" at 2169,-1064.84 h60
  text ".Print_Date" at 2898,-1064.84 h60
  text "GENERATED    :" at 3767.5,-1064.84 h60
M9 Title Sheet:
  drawing of 57 lines, arcs and shapes, not listed
  text "1" at 739.84,8036.5 h70
  text "2" at 3235.5,8036.5 h70
  text "3" at 5724.84,8036.5 h70
  text "4" at 8231.51,8036.5 h70
  text "5" at 10730.5,8036.5 h70
  text "6" at 13235.5,8036.5 h70
  text "A" at -416.5,6893.5 h70
  text "A" at 14383.5,6893.5 h70
  text "B" at -416.5,4513.5 h70
  text "B" at 14383.5,4513.5 h70
  text "C" at -416.5,2138.5 h70
  text "C" at 14383.5,2138.5 h70
  text "PROJECT TITLE:" at 11343.5,277.5 h45
  text ".PRJ_Title" at 11393.5,144.17 h70
  text "DESIGNED FOR:" at 11343.5,-23.5 h45
  text ".PRJ_Customer" at 11393.5,-163.5 h70
  text "D" at -416.5,-231.5 h70
  text "D" at 14383.5,-231.5 h70
  text "FILE NAME:" at 11343.5,-323.5 h45
  text ".PCB_File_Name_No_Path" at 11393.5,-443.5 h70
  text "Texas Instruments (TI) and/or its licensors do not warrant the accuracy or completeness of this specification" at 6374,-605.34 h45
  text "ENGINEER:" at 11343.5,-613.5 h45
  text "LAYOUT BY:" at 12848.5,-613.5 h45
  text "or any information contained therein. TI and/or its licensors do not warrant that this design will meet" at 6329.01,-718 h45
  text ".PRJ_Engineer" at 11393.5,-768.49 h70
  text ".PCB_Layout" at 12899,-768.49 h70
  text "the specifications, will be suitable for your application or fit for any particular purpose, or will operate in" at 6329.01,-830.67 h45
  text "ALTIUM DESIGNER VERSION:" at 12848.5,-923.5 h45
  text "an implementation. TI and/or its licensors do not warrant that the design is production worthy. You should" at 6329.01,-943.33 h45
  text "completely validate and test your design implementation to confirm the system functionality for your application." at 6374,-1056 h45
  text ".print_Scale" at 11393.5,-1056.83 h70
  text ".Application_BuildNumber" at 12899,-1056.83 h70
  text "1" at 739.84,-1263.5 h70
  text "2" at 3235.5,-1263.5 h70
  text "3" at 5724.84,-1263.5 h70
  text "4" at 8231.51,-1263.5 h70
  text "5" at 10730.5,-1263.5 h70
  text "WO# 306274-6263-D" at 13235.5,-1263.5 h70
M10 Fab Notes:
  drawing of 189 lines, arcs and shapes, not listed
  text "DESIGN INFORMATION" at 12381.02,6028 h60
  text "ADDITIONAL FAB NOTES:" at 187.48,5995 h60
  text "MIN. TRACK WIDTH:" at 11736.46,5848 h60
  text "6" at 12832.7,5848 h60
  text "MIL" at 12987.46,5848 h60
  text "1. SOLDERMASK CLEARANCE IS GIVEN AS SAME AS PAD SIZE FOR ALL SMT COMPONENT EXCEPT Q1, Q2 & Q3." at 182.35,5837.31 h60
  text "VENDOR SHALL OVERSIZE THE MASK CLEARANCES. AS PER THEIR MANUFACTURE CAPABILITIES" at 294.73,5723.41 h60
  text "MIN. CLEARANCE:" at 11736.46,5716 h60
  text "MIL" at 12983.19,5713.35 h60
  text "5" at 12836.43,5712.24 h60
  text "MIN. VIA PAD SIZE:" at 11736.46,5584 h60
  text "18" at 12802.71,5584 h60
  text "MIL" at 12987.46,5584 h60
  text "2. IGNORE THE V-SCORE NOTE INCASE OF NO PANEL REQUIREMENT FOR THIS DESIGN." at 182.35,5545.27 h60
  text "0.05mm (2MIL)" at 12431.46,5442.29 h60
  text "MINIMUM ANNULAR RING" at 11407.23,5438 h60
  text "EXTERNAL" at 13139.46,5438 h60
  text "PER" at 11607.23,5320 h60
  text "IPC-D-275 CLASS 2 LEVEL C" at 11827.23,5320 h60
  text "MIL, HOLES" at 13315.46,5207.71 h60
  text "+/-" at 12923,5207 h60
  text "+/-" at 13777,5207 h60
  text "REGISTRATION TOLERANCES:" at 11407.23,5202 h60
  text "METAL" at 12607,5202 h60
  text "5" at 13183.2,5202 h60
  text "3" at 14016.2,5202 h60
  text "MIL" at 14132.46,5202 h60
  text "+/-" at 13777,5089 h60
  text "HOLE SIZE TOLERANCE (UNLESS OTHERWISE SPECIFIED):" at 11407.23,5084 h60
  text "3" at 14016.2,5084 h60
  text "MIL" at 14132.46,5084 h60
  text "MATERIAL:" at 11332.46,4874.54 h60
  text "FR-4 High Tg" at 12318.9,4734.21 h60
  text "FR-408" at 11753.46,4725.64 h60
  text "OTHER" at 13241.46,4725.64 h60
  text "X" at 12164,4722 h60
  text "62 MIL (1.6mm) +/-10%" at 12073.56,4562.92 h60
  text "THICKNESS:" at 11407.23,4558.64 h60
  text "X" at 11945.4,4558.64 h60
  text "OTHER" at 13358.46,4558.64 h60
  text "TOLERANCE:" at 11407.23,4400.64 h60
  text "X" at 12246.53,4400.64 h60
  text "ANSI IPC-6012 TYPE 3 CLASS 2" at 12433.48,4400.64 h60
  text "OTHER +/-" at 12433.46,4244.64 h60
  text "BOW & TWIST:" at 11407.23,4087.64 h60
  text "X" at 12246.53,4087.64 h60
  text "ANSI IPC-6012 TYPE 3 CLASS 2" at 12433.48,4087.64 h60
  text "OTHER +/-" at 12433.46,3929.13 h60
  text "DRILLING:" at 11332.46,3790.64 h60
  text "REFERENCE:" at 11407.23,3673.64 h60
  text "X" at 12055.46,3673.64 h60
  text "AS SHOWN" at 12242.46,3673.64 h60
  text "X" at 12956.46,3673.64 h60
  text "NC_DRILL FILES" at 13093.46,3673.64 h60
  text "PTH MIN COPPER THICKNESS:" at 11407.23,3515.64 h60
  text "X" at 12757.46,3515.64 h60
  text "1MIL" at 12894.46,3515.64 h60
  text "OTHER" at 13391.46,3515.64 h60
  text "BOARD FINISH:" at 11332.46,3356.64 h60
  text "SILKSCREEN:" at 11487.68,3238.64 h60
  text "X" at 12436.46,3238.64 h60
  text "TOP" at 12562.46,3238.64 h60
  text "X" at 12946.46,3238.64 h60
  text "BOTTOM" at 13073.46,3238.64 h60
  text "SILKSCREEN COLOR:" at 11487.68,3071.64 h60
  text "X" at 12435.42,3071.64 h60
  text "WHITE" at 12562.46,3071.64 h60
  text "OTHER" at 13073.46,3071.64 h60
  text "X" at 12566.42,2912.44 h60
  text "GREEN" at 12693.46,2912.44 h60
  text "OTHER" at 13311.46,2912.44 h60
  text "SOLDER RESIST COLOR:" at 11487.68,2901.64 h60
  text "X" at 12566.42,2742.44 h60
  text "MATTE" at 12693.46,2742.44 h60
  text "SEMI-GLOSS" at 13311,2741.8 h60
  text "IMMERSION GOLD (ENIG)" at 12393.46,2553.92 h60
  text "ENEPIG" at 13731,2550.64 h60
  text "SURFACE FINISH:" at 11332.46,2549.64 h60
  text "X" at 12206.51,2549.64 h60
  text "IMM. TIN/SILVER OR EQUIV" at 11662,2392.64 h60
  text "OTHER" at 13093.46,2392.64 h60
  text "ARRAY/PANEL:" at 11332.46,2213.64 h60
  text "CUT AND TRIM PER M1 BOARD OUTLINE" at 12393.46,2209.35 h60
  text "N.C. ROUTE" at 12393.46,2057.64 h60
  text "X" at 13072.46,2057.64 h60
  text "V. SCORE" at 13259.46,2057.64 h60
  text "CERTIFICATION:" at 11332.46,1920.64 h60
  text "MATERIALS AND WORKMANSHIP FOR ALL PCBS" at 12057.46,1920.64 h60
  text "TO MEET OR EXCEED THE REQUIREMENTS OF:" at 12057.46,1822.64 h60
  text "X" at 11683.96,1686.13 h60
  text "ANSI IPC-A-600F CLASS ->" at 11822.96,1686.13 h60
  text "X" at 13462.02,1686.13 h60
  text "2" at 13580.96,1686.14 h60
  text "1" at 13265.96,1684.64 h60
  text "3" at 13934.96,1684.64 h60
  text "X" at 11686.02,1526.64 h60
  text "UL 94V-0" at 11822.96,1526.64 h60
  text "X" at 12498.02,1526.64 h60
  text "RoHS" at 12634.96,1526.64 h60
  text "OTHER" at 13279.36,1526.64 h60
  text "PER ORDER" at 13676.42,1526.64 h60
  text "ADDITIONAL REQUIREMENTS:" at 11332.46,1385.64 h60
  text "MICROSECTION:" at 11407.23,1270.64 h60
  text "YES" at 12312.96,1270.64 h60
  text "REQUIRED" at 13174.46,1114.49 h60
  text "BARE BOARD ELEC. TEST:" at 11407.23,1111.64 h60
  text "NONE" at 12712.96,1111.64 h60
  text "X" at 13047.46,1111.64 h60
  text "PER ORDER" at 13766.46,1111.64 h60
  text "MANUFACTURER'S UL:" at 11407.23,954.64 h60
  text "RAIL" at 12572.96,950.35 h60
  text "METAL" at 13064.77,950.35 h60
  text "X" at 13440,950 h60
  text "SILK" at 13576.46,950.35 h60
M11 Gerber Information:
  lines w10: -292,-930.17 6308,-930.17 ; -292,-726.83 6310,-726.83 ; -292,-523.5 -292,-1133.5 3713,-1133.5 6310,-1133.5 6310,-523.5 -291.5,-523.5 -291.5,-1133.5 1284,-1133.5 ; 2173,-1133.5 2173,-523.5 ; 3440,-726.83 3440,-523.5 ; 4280,-726.83 4280,-523.5 ; 4902,-1140 4902,-937.17
  text "ALL ARTWORK VIEWED FROM TOP SIDE" at -228.5,-655.67 h60
  text "BOARD #:" at 2248,-655.67 h60
  text ".PRJ_Number" at 2793.5,-655.67 h60
  text "REV:" at 3638,-655.67 h60
  text ".PCB_Rev" at 3929.5,-655.67 h60
  text "SVN REV:" at 4476,-655.67 h60
  text ".VersionControl_RevNumber" at 4982,-655.67 h60
  text "LAYER NAME =" at -228.5,-858.49 h60
  text "TID #:" at 2248,-859 h60
  text ".TID" at 2793.5,-859 h60
  text "GENERATED    :" at 2250,-1064.34 h60
  text ".Print_Date" at 3119.5,-1064.34 h60
  text ".Print_Time" at 3848.5,-1064.34 h60
  text "TEXAS INSTRUMENTS" at 5113,-1064.34 h60
M12 Stackup:
  drawing of 399 lines, arcs and shapes, not listed
  text "DRILL CHART:" at 5444.17,6042.5 h60
  text "STACKUP:" at 5924.61,4707.17 h60
  text "Layer" at 5976.47,4552.68 h60
  text "Name" at 6386.38,4552.68 h60
  text "Material" at 7326.12,4552.68 h60
  text "Thickness" at 8185.89,4552.68 h60
  text "Constant" at 8835.73,4552.68 h60
  text "Board Layer Stack" at 9405.59,4552.68 h60
  text "1" at 5976.47,4432.68 h60
  text "Top Overlay" at 6386.38,4432.68 h60
  text "2" at 5976.47,4312.68 h60
  text "Top Solder" at 6386.38,4312.68 h60
  text "Solder Resist" at 7326.12,4312.68 h60
  text "4" at 8835.73,4312.68 h60
  text "0.5OZ+PLATING" at 8140.17,4196.13 h50
  text "3" at 5976.47,4192.68 h60
  text "Top Layer" at 6386.38,4192.68 h60
  text "Copper" at 7326.12,4192.68 h60
  text "4" at 5976.47,4072.68 h60
  text "Dielectric 1" at 6386.38,4072.68 h60
  text "FR-4 High Tg" at 7326.12,4072.68 h60
  text "4.3" at 8835.73,4072.68 h60
  text "TBD" at 8355.54,4065.82 h60
  text "5" at 5976.47,3952.68 h60
  text "GND" at 6386.38,3952.68 h60
  text "Copper" at 7326.12,3952.68 h60
  text "1OZ" at 8355.54,3949.14 h60
  text "6" at 5976.47,3832.68 h60
  text "Dielectric 2" at 6386.38,3832.68 h60
  text "FR-4 High Tg" at 7326.12,3832.68 h60
  text "4.3" at 8835.73,3832.68 h60
  text "TBD" at 8355.54,3822.17 h60
  text "7" at 5976.47,3712.68 h60
  text "Signal Layer 1" at 6386.38,3712.68 h60
  text "Copper" at 7326.12,3712.68 h60
  text "1OZ" at 8355.54,3710.86 h60
  text "8" at 5976.47,3592.68 h60
  text "Dielectric 3" at 6386.38,3592.68 h60
  text "FR-4 High Tg" at 7326.12,3592.68 h60
  text "4.3" at 8835.73,3592.68 h60
  text "TBD" at 8355.54,3583.88 h60
  text "9" at 5976.47,3472.68 h60
  text "Signal Layer 2" at 6386.38,3472.68 h60
  text "Copper" at 7326.12,3472.68 h60
  text "1OZ" at 8355.54,3471.94 h60
  text "10" at 5976.47,3352.68 h60
  text "Dielectric 4" at 6386.38,3352.68 h60
  text "FR-4 High Tg" at 7326.12,3352.68 h60
  text "4.3" at 8835.73,3352.68 h60
  text "TBD" at 8355.54,3344.97 h60
  text "11" at 5976.47,3232.68 h60
  text "PWR Split" at 6386.38,3232.68 h60
  text "Copper" at 7326.12,3232.68 h60
  text "1OZ" at 8355.54,3231.4 h60
  text "12" at 5976.47,3112.68 h60
  text "Dielectric 5" at 6386.38,3112.68 h60
  text "FR-4 High Tg" at 7326.12,3112.68 h60
  text "4.3" at 8835.73,3112.68 h60
  text "TBD" at 8355.54,3104.42 h60
  text "0.5OZ+PLATING" at 8139.71,2996.09 h50
  text "13" at 5976.47,2992.68 h60
  text "Bottom Layer" at 6386.38,2992.68 h60
  text "Copper" at 7326.12,2992.68 h60
  text "14" at 5976.47,2872.68 h60
  text "Bottom Solder" at 6386.38,2872.68 h60
  text "Solder Resist" at 7326.12,2872.68 h60
  text "4" at 8835.73,2872.68 h60
  text "15" at 5976.47,2752.68 h60
  text "Bottom Overlay" at 6386.38,2752.68 h60
  text "THIS IS A NON-IMPEDANCE CONTROLLED BOARD" at 5917.99,2571.21 h60
M13 Component Bodies Top:
  text ".Layer_Name" at 577,-858.49 h60
M14 Component Bodies Bottom:
  text ".Layer_Name" at 577,-858.49 h60
M15 Courtyards Top:
  text ".Layer_Name" at 577,-858.49 h60
M16 Courtyards Bottom:
  text ".Layer_Name" at 577,-858.49 h60
Drill Drawing:
  circle w10: c5543.69,5452.97 r33.33
  lines w10: 5510.36,5269.64 5577.02,5269.64 5577.02,5336.31 5510.36,5336.31 5510.36,5269.64 ; 5510.36,5586.31 5527.02,5586.31 5543.69,5569.64 5560.36,5586.31 5577.02,5586.31 5560.36,5602.97 5577.02,5619.64 5560.36,5619.64 5543.69,5636.31 5527.02,5619.64 5510.36,5619.64 5527.02,5602.97 5510.36,5586.31 ; 5510.36,5786.31 5577.02,5786.31 5543.69,5719.64 5510.36,5786.31
  lines w15: 5450.57,5224.64 11013.07,5224.64 ; 5450.57,5824.64 11013.07,5824.64 ; 6001.44,5074.64 6001.44,5974.64 ; 6699.26,5074.64 6699.26,5974.64 ; 8044.86,5074.64 8044.86,5974.64 ; 8550.74,5074.64 8550.74,5974.64 ; 9284.54,5074.64 9284.54,5974.64 ; 10390.22,5074.64 10390.22,5974.64 ; 5450.57,5074.64 11013.07,5074.64 11013.07,5974.64 5450.57,5974.64 5450.57,5074.64
  text "Symbol" at 5540.57,5869.64 h72
  text "Hit Count" at 6046.44,5869.64 h72
  text "Finished Hole Size" at 6744.26,5869.64 h72
  text "Plated" at 8089.86,5869.64 h72
  text "Hole Type" at 8595.74,5869.64 h72
  text "Tolerance (Mil)" at 9329.54,5869.64 h72
  text "Tenting" at 10435.22,5869.64 h72
  text "835" at 6046.44,5719.64 h60
  text "8.00mil (0.203mm)" at 6744.26,5719.64 h60
  text "PTH" at 8089.86,5719.64 h60
  text "Round" at 8595.74,5719.64 h60
  text "69" at 6046.44,5569.64 h60
  text "8.01mil (0.203mm)" at 6744.26,5569.64 h60
  text "PTH" at 8089.86,5569.64 h60
  text "Round" at 8595.74,5569.64 h60
  text "58" at 6046.44,5419.64 h60
  text "40.00mil (1.016mm)" at 6744.26,5419.64 h60
  text "PTH" at 8089.86,5419.64 h60
  text "Round" at 8595.74,5419.64 h60
  text "40" at 6046.44,5269.64 h60
  text "51.18mil (1.300mm)" at 6744.26,5269.64 h60
  text "PTH" at 8089.86,5269.64 h60
  text "Round" at 8595.74,5269.64 h60
  text "1002 Total" at 6046.44,5119.64 h60
  text "FAB" at 577,-858.49 h60

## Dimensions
0,0 to 0,4500 on M2 Board Dimensions
0,0 to 5500,0 on M2 Board Dimensions
258.26,-404.49 to 1258.26,-404.49 on M2 Board Dimensions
